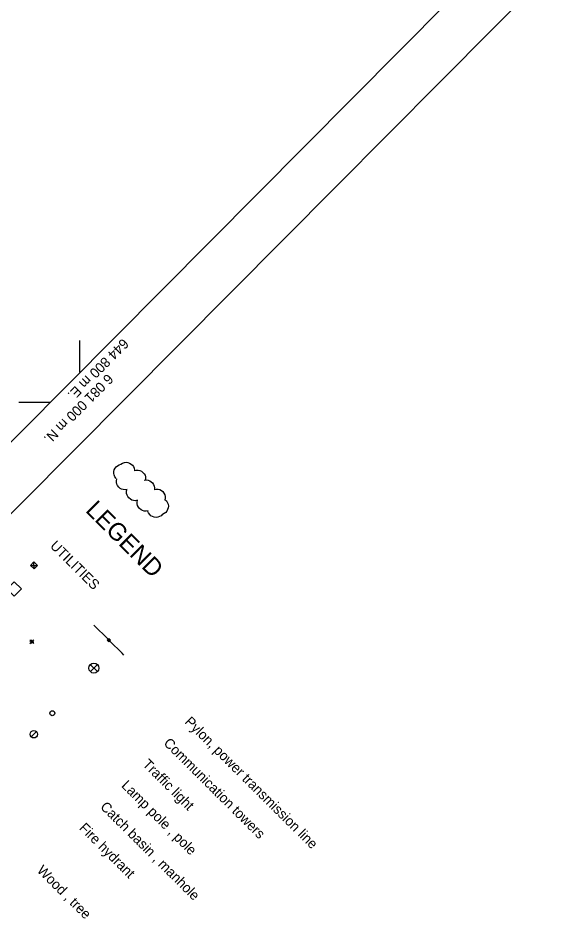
# Model space of a CAD drawing. Extents: x 642515 to 647219, y 6080136 to 6084356.
# Drawn here: x 644775.3 to 644993.9, y 6080786.9 to 6081153.8 of the extents above; entities that cross this region are included whole.
import ezdxf

# ---------------------------------------------------------------- set-up
doc = ezdxf.new("R2010")
doc.units = 0
for name, color, linetype in [('Level 21', 7, 'Continuous'), ('Level 34', 7, 'Continuous'), ('Level 36', 7, 'Continuous'), ('Level 44', 7, 'Continuous'), ('Level 60', 7, 'Continuous'), ('Level 61', 7, 'Continuous'), ('Level 63', 7, 'Continuous')]:
    doc.layers.add(name, color=color, linetype=linetype)

msp = doc.modelspace()

# ---------------------------------------------------------------- linework, layer by layer
at = {"layer": 'Level 21'}
for p, q in [((644781.51, 6080904.75), (644779.92, 6080903.16)), ((644779.94, 6080904.75), (644781.53, 6080903.19)), ((644780.71, 6080903.22), (644780.74, 6080904.71)), ((644779.95, 6080903.98), (644781.46, 6080903.96))]:
    msp.add_line(p, q, dxfattribs=at)
at = {"layer": 'Level 34'}
for p, q in [((644806.99, 6080891.97), (644804.14, 6080894.79)), ((644806.98, 6080894.79), (644804.17, 6080891.95))]:
    msp.add_line(p, q, dxfattribs=at)
msp.add_lwpolyline([(644773.68, 6080922.26), (644770.84, 6080925.07), (644773.67, 6080927.92), (644776.5, 6080925.09)], close=True, dxfattribs=at)
msp.add_circle((644805.58, 6080893.36), 2, dxfattribs=at)
at = {"layer": 'Level 36'}
for p, q in [((644780.16, 6080934.54), (644782.99, 6080934.53)), ((644781.58, 6080933.13), (644781.56, 6080935.95)), ((644811.24, 6080904.92), (644805.58, 6080910.55)), ((644816.91, 6080899.29), (644811.96, 6080904.22)), ((644817.61, 6080898.6), (644816.91, 6080899.29)), ((644780.41, 6080865.8), (644782.53, 6080867.91))]:
    msp.add_line(p, q, dxfattribs=at)
for points in [[(644781.58, 6080933.13), (644780.16, 6080934.54), (644781.56, 6080935.95), (644782.99, 6080934.53)], [(644812.29, 6080904.59), (644811.61, 6080903.86), (644810.89, 6080904.57), (644811.6, 6080905.27)]]:
    msp.add_lwpolyline(points, close=True, dxfattribs=at)
msp.add_lwpolyline([(644811.64, 6080904.02), (644811.06, 6080904.57), (644811.17, 6080904.69), (644811.75, 6080904.17), (644811.88, 6080904.3), (644811.35, 6080904.86), (644811.48, 6080904.99), (644812.02, 6080904.45), (644812.13, 6080904.57), (644811.63, 6080905.09)], dxfattribs=at)
for centre, radius in [((644788.91, 6080875.28), 1), ((644781.49, 6080866.86), 1.5)]:
    msp.add_circle(centre, radius, dxfattribs=at)
at = {"layer": 'Level 44'}
for points in [[(644814.47, 6080969.36), (644813.94, 6080970.02), (644813.69, 6080970.78), (644813.53, 6080971.42), (644813.56, 6080972.13), (644813.71, 6080972.85), (644814.1, 6080973.53), (644814.46, 6080974.05), (644815.01, 6080974.49), (644815.66, 6080974.86), (644816.35, 6080975.07)], [(644816.33, 6080975.1), (644817.01, 6080975.55), (644817.8, 6080975.77), (644818.45, 6080975.87), (644819.15, 6080975.77), (644819.87, 6080975.53), (644820.5, 6080975.12), (644821.02, 6080974.72), (644821.41, 6080974.14), (644821.71, 6080973.46), (644821.86, 6080972.76)], [(644821.76, 6080972.55), (644822.56, 6080972.74), (644823.37, 6080972.69), (644824.02, 6080972.58), (644824.64, 6080972.24), (644825.24, 6080971.79), (644825.71, 6080971.19), (644826.06, 6080970.64), (644826.23, 6080969.97), (644826.29, 6080969.22), (644826.19, 6080968.51)], [(644818.97, 6080964.98), (644818.14, 6080964.84), (644817.32, 6080964.92), (644816.69, 6080965.06), (644816.08, 6080965.42), (644815.53, 6080965.88), (644815.07, 6080966.51), (644814.74, 6080967.07), (644814.61, 6080967.78), (644814.57, 6080968.49), (644814.71, 6080969.2)], [(644825.71, 6080968.7), (644826.56, 6080968.81), (644827.35, 6080968.67), (644827.98, 6080968.48), (644828.55, 6080968.08), (644829.1, 6080967.56), (644829.5, 6080966.91), (644829.78, 6080966.32), (644829.87, 6080965.61), (644829.84, 6080964.88), (644829.81, 6080964.77)], [(644823.06, 6080960.64), (644822.26, 6080960.46), (644821.45, 6080960.55), (644820.8, 6080960.71), (644820.21, 6080961.06), (644819.62, 6080961.55), (644819.17, 6080962.17), (644818.87, 6080962.73), (644818.71, 6080963.41), (644818.7, 6080964.17), (644818.82, 6080964.88)], [(644829.74, 6080964.96), (644830.56, 6080965.12), (644831.38, 6080965.04), (644832.02, 6080964.89), (644832.63, 6080964.53), (644833.19, 6080964.09), (644833.65, 6080963.46), (644833.96, 6080962.87), (644834.11, 6080962.19), (644834.14, 6080961.46), (644834, 6080960.75)], [(644827.32, 6080956.41), (644826.52, 6080956.23), (644825.71, 6080956.32), (644825.07, 6080956.48), (644824.46, 6080956.83), (644823.88, 6080957.32), (644823.44, 6080957.93), (644823.1, 6080958.49), (644822.97, 6080959.19), (644822.93, 6080959.94), (644823.08, 6080960.63)], [(644834.05, 6080960.92), (644834.67, 6080960.35), (644835.09, 6080959.63), (644835.33, 6080959.03), (644835.42, 6080958.32), (644835.36, 6080957.58), (644835.11, 6080956.88), (644834.85, 6080956.27), (644834.38, 6080955.74), (644833.77, 6080955.3), (644833.12, 6080954.98)], [(644833.12, 6080955.02), (644832.51, 6080954.43), (644831.81, 6080954.07), (644831.18, 6080953.83), (644830.47, 6080953.79), (644829.75, 6080953.86), (644829.03, 6080954.16), (644828.45, 6080954.44), (644827.93, 6080954.94), (644827.52, 6080955.54), (644827.22, 6080956.2)]]:
    msp.add_lwpolyline(points, dxfattribs=at)
at = {"layer": 'Level 60'}
for p, q in [((644800, 6081011.94), (644800, 6081024.63)), ((644775.46, 6081000), (644788.06, 6081000))]:
    msp.add_line(p, q, dxfattribs=at)
for points in [[(643756.23, 6083485.06), (645517.55, 6081734.46), (644300.6, 6080509.08), (642538.79, 6082260.16)], [(645532.22, 6081719.89), (645869.07, 6081384.98), (644651.68, 6080160.13), (644314.78, 6080494.98)]]:
    msp.add_lwpolyline(points, close=True, dxfattribs=at)

# ---------------------------------------------------------------- texts
at = {"layer": 'Level 61'}
for s, p in [('644 800 m E.', (644817.11, 6081025.76)), ('6 081 000 m N.', (644810.95, 6081011.59))]:
    msp.add_text(s, height=4, rotation=225.175, dxfattribs=at).set_placement(p)
at = {"layer": 'Level 63'}
for s, height, p in [('LEGEND', 7, (644801.84, 6080956.24)), ('UTILITIES', 4, (644787.75, 6080942.05)), ('Pylon, power transmission line', 4, (644841.7, 6080871.53)), ('Communication towers', 4, (644833.24, 6080862.99)), ('Traffic light', 4, (644824.78, 6080854.48)), ('Lamp pole , pole', 4, (644816.32, 6080845.98)), ('Catch basin , manhole', 4, (644807.85, 6080837.46)), ('Fire hydrant', 4, (644799.4, 6080828.95)), ('Wood , tree', 4, (644782.48, 6080811.95))]:
    msp.add_text(s, height=height, rotation=315.1529, dxfattribs=at).set_placement(p)

doc.saveas('drawing.dxf')
